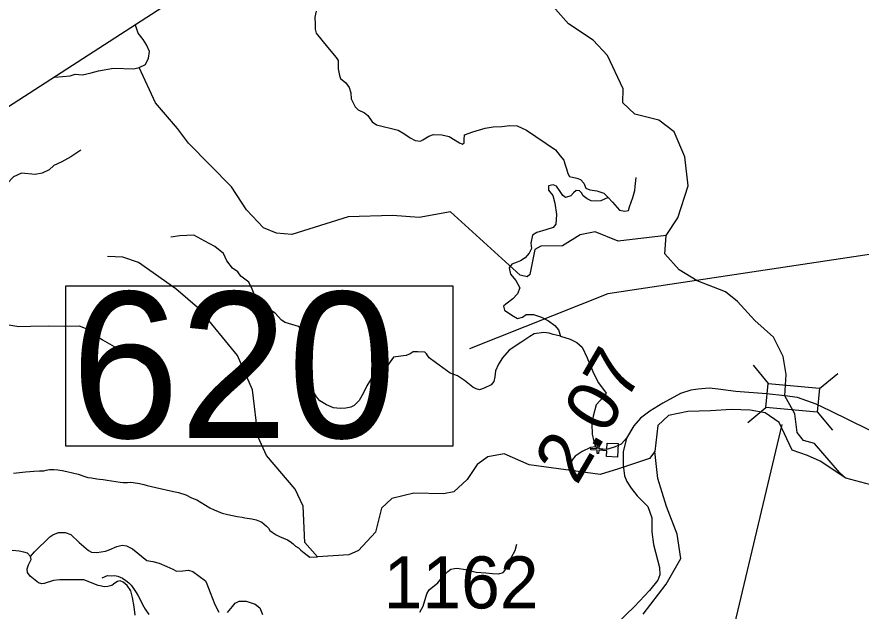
# Model space of a CAD drawing. Extents: x 1248089 to 1457196, y 820910 to 988753.
# Drawn here: x 1252912 to 1261020, y 869456 to 875158 of the extents above; entities that cross this region are included whole.
import ezdxf

# ---------------------------------------------------------------- set-up
doc = ezdxf.new("R2010")
doc.units = 0
for name, color, linetype in [('Exist Boundary Political CountyLine', 7, 'Continuous'), ('Exist Cultural Church CELL', 7, 'Continuous'), ('Exist Hydrographic Creek Single Shore', 7, 'Continuous'), ('Exist Hydrographic Misc Water Feature', 7, 'Continuous'), ('Exist Road Non-System Type 51', 7, 'Continuous'), ('Exist Road Secondary Structure Standard Bridge CELL', 7, 'Continuous'), ('Exist Road Secondary Structure Standard Bridge Number Label', 7, 'Continuous'), ('Exist Road Secondary Type 41 Attributed', 7, 'Continuous'), ('Exist Road Secondary Type 51 Attributed', 7, 'Continuous'), ('Prop GRAU CAT1 Cell', 7, 'Continuous'), ('Prop Lane Lines', 7, 'Continuous')]:
    doc.layers.add(name, color=color, linetype=linetype)

msp = doc.modelspace()

# ---------------------------------------------------------------- linework, layer by layer
at = {"layer": 'Exist Boundary Political CountyLine'}
msp.add_lwpolyline([(1272087, 895656.9), (1271079.1, 894111.7), (1270645.1, 893445.4), (1270071.1, 892564.9), (1269839.1, 892211.5), (1269310.1, 891393.6), (1268930.1, 890815.9), (1268447.1, 890082.3), (1267988.1, 889388.8), (1267175.1, 888170.6), (1266759.1, 887546.2), (1266505.1, 887165.9), (1265873.1, 886219.1), (1264802.2, 884614.3), (1263985.2, 883390.3), (1262147.2, 880635.4), (1261769.2, 880069.6), (1260071.2, 878960.9), (1254161.3, 875151.2), (1250985.3, 873104.2), (1248224.3, 871303)], dxfattribs=at)
at = {"layer": 'Exist Cultural Church CELL'}
msp.add_lwpolyline([(1258574.5, 870938.7), (1258576.9, 870995.6), (1258500.9, 870999), (1258499.4, 870967), (1258483.5, 870967.7), (1258484.9, 870999.7), (1258424.8, 871002.4), (1258425.5, 871018.4), (1258485.6, 871015.7), (1258487, 871047.7), (1258503, 871047), (1258501.6, 871015), (1258577.6, 871011.6), (1258580.3, 871069.2), (1258686.7, 871064.5), (1258680.9, 870934)], close=True, dxfattribs=at)
at = {"layer": 'Exist Hydrographic Creek Single Shore'}
for points in [[(1259326.3, 873814.3), (1259224.3, 874056), (1259077.3, 874167.3), (1258845.3, 874224.5), (1258731.3, 874335.1), (1258734.4, 874469.5), (1258584.4, 874787.8), (1258446.4, 874935), (1258208.3, 875090.7), (1258038.3, 875287.8), (1258016.3, 875386.7), (1257961.3, 875506.1), (1257896.3, 875572.9), (1257723.2, 875652), (1257687.3, 875895.6), (1257622.3, 875939.5), (1257281.3, 876005.5), (1257292.3, 876080.8), (1257395.3, 876219.8), (1257399.3, 876354.4), (1257352.3, 876496.5), (1257381.2, 876945.6), (1257399.3, 877004.4), (1257408.9, 877244.7)], [(1254086.2, 874671.1), (1254148.2, 874701.5), (1254177.9, 874760.8), (1254185.3, 874825.7), (1254155.7, 874888.7), (1254124.1, 874942.5), (1254077.8, 875001.8), (1254050.4, 875079.7)], [(1254559.3, 873945.9), (1254455.3, 874085.9), (1254244.3, 874333.1), (1254086.2, 874671.1)], [(1259148.4, 873059.6), (1258688.3, 873006.4), (1258465.3, 873096.2), (1258323.3, 873066.2), (1258153.3, 872961.3), (1257945.3, 872958.9), (1257885.3, 872927.3), (1257837.4, 872685.4), (1257812.3, 872662.8), (1257746.3, 872680.5), (1257077.3, 873288.1), (1256776.3, 873231.8), (1256518.4, 873253.5), (1256092.4, 873239), (1255554.3, 873069.2), (1255404.3, 873082), (1255280.4, 873133.8), (1255118.4, 873307.7), (1254974.3, 873527.3), (1254559.3, 873945.9)], [(1259148.4, 873059.6), (1259261.3, 873231.3), (1259360.4, 873537.9), (1259326.3, 873814.3)], [(1260287.6, 871522.6), (1260301, 871727.8), (1260271.2, 871899.7), (1260178.2, 872085.9), (1260000.7, 872246.1), (1259834.1, 872425.8), (1259718.4, 872519.6), (1259445.4, 872626.8), (1259273.3, 872732), (1259135.3, 872885.9), (1259148.4, 873059.6)], [(1260813.5, 870786.7), (1260573.6, 871063.1), (1260467.6, 871093.4), (1260404.8, 871171.3), (1260383.2, 871348.9), (1260287.6, 871522.6)], [(1260872.4, 870730.4), (1260626.5, 870896.2), (1260503.4, 870947.9), (1260357, 871001), (1260231.5, 871267.3), (1260099.6, 871358.3), (1259954.6, 871384.3), (1259775, 871390.8), (1259573.8, 871377.8), (1259356.5, 871370.3), (1259170.4, 871332.4), (1259067.4, 871236), (1259038.3, 870988.3)], [(1258926.5, 869427.1), (1259146.4, 869715.2), (1259287.1, 869960.8), (1259254.6, 870194.7), (1259150.8, 870460.3), (1259068.6, 870728.8), (1259038.3, 870988.3)], [(1261475.5, 870508.2), (1261162.5, 870655.7), (1260872.4, 870730.4), (1260813.5, 870786.7)]]:
    msp.add_lwpolyline(points, dxfattribs=at)
at = {"layer": 'Exist Hydrographic Misc Water Feature'}
for points in [[(1253276.3, 874580.8), (1253422.5, 874593.2), (1253471, 874607.8), (1253542.1, 874603.2), (1253625.5, 874621.8), (1253695.9, 874640.3), (1253840.7, 874666.9), (1254037, 874658.8), (1254086.2, 874671.1)], [(1259038.3, 870988.3), (1258988.6, 870921.2), (1258690.4, 870820.1), (1258513.4, 870767.8), (1257832.4, 870860.3), (1257593.4, 870966.8), (1257434.4, 870937.1), (1257332.4, 870863.7), (1257236.5, 870717.9), (1257108.4, 870602.2), (1257008.4, 870581.3), (1256724.4, 870587), (1256514.4, 870535.4), (1256412.5, 870445.5), (1256356.4, 870213.6), (1256193.5, 870036.3), (1256100.5, 869995.5), (1255800.4, 869978.5), (1255678.4, 870115.5), (1255662.4, 870463.8), (1255583.4, 870626.2), (1255308.3, 870950.2), (1255229.4, 871125.7), (1255174.3, 871579.8), (1255032.3, 871907.7), (1254668.4, 872351.5), (1254440.4, 872549.9), (1254079.4, 872800), (1253931.3, 872852.2), (1253781.3, 872858.5)], [(1252879.5, 870781), (1252937.6, 870787.5), (1252995.9, 870794.1), (1253038, 870796.9), (1253075.9, 870798), (1253130.3, 870802.6), (1253170.3, 870803.5), (1253194.4, 870808.9), (1253226.5, 870814.1), (1253246.7, 870815.5), (1253268.6, 870815), (1253304.6, 870812.1), (1253348.4, 870804.9), (1253392.2, 870795.8), (1253499.6, 870769.1), (1253565.1, 870749.3), (1253594.8, 870738.5), (1253628.8, 870733.7), (1253680.5, 870724.2), (1253704.5, 870723.6), (1253742.5, 870718.7), (1253780.3, 870711.7), (1253820.3, 870706.7), (1253862, 870699.6), (1253904, 870694.5)], [(1253904, 870694.5), (1253933.9, 870691.7), (1253973.9, 870690.7), (1254006, 870692), (1254028, 870691.3), (1254089.7, 870681.7), (1254131.6, 870670.6), (1254163.2, 870661.8), (1254205.2, 870652.7), (1254246.9, 870641.7), (1254416.1, 870605.3), (1254465.8, 870593.9), (1254535.3, 870572.2), (1254590.6, 870542.8), (1254640, 870523.4), (1254722.7, 870473.3), (1254766.2, 870448.1), (1254807.8, 870429.1), (1254885, 870397.1), (1254936.7, 870381.7), (1254982.5, 870374.4), (1255028.2, 870365.3), (1255076.1, 870358), (1255101.9, 870351.5), (1255169.7, 870341.6), (1255211.6, 870332.5), (1255241.3, 870319.8), (1255265, 870309.1), (1255288.6, 870290.6), (1255308, 870272), (1255327.5, 870251.5), (1255341.1, 870231.2), (1255364.5, 870212.5), (1255402.1, 870189.6), (1255433.5, 870172.8), (1255510.7, 870140.8), (1255538.4, 870124), (1255565.8, 870101.2), (1255589.3, 870080.7), (1255617, 870061.9), (1255640.3, 870041.3), (1255687.4, 870002.1), (1255726.7, 869975), (1255800.4, 869978.5)], [(1253732.1, 869776.3), (1253782.8, 869797), (1253818.7, 869796.1), (1253848.8, 869797.3), (1253880.7, 869790.5), (1253928.1, 869771.3), (1253959.6, 869750.4), (1253987.2, 869727.7), (1254008.5, 869705.1), (1254031.8, 869674.5), (1254056.8, 869635.8), (1254075.9, 869603.3), (1254100.9, 869560.7), (1254119.8, 869520.2), (1254144.7, 869475.5), (1254179.4, 869422.5)]]:
    msp.add_lwpolyline(points, dxfattribs=at)
at = {"layer": 'Exist Road Non-System Type 51'}
for points in [[(1255787.8, 875212.6), (1255773.7, 875156.1), (1255776, 875087.8), (1255778.4, 875040.7), (1255787.8, 875000.7), (1255896.1, 874866.5), (1255977.8, 874769.1), (1255996.6, 874740.9), (1255996.6, 874658.4), (1256010.8, 874597.2), (1256020.2, 874566.6), (1256071.9, 874524.2), (1256104.9, 874481.8), (1256119, 874430), (1256123.7, 874371.1), (1256161.4, 874295.8), (1256189.6, 874265.2), (1256250.8, 874236.9), (1256283.7, 874211), (1256323.7, 874149.8), (1256366.1, 874123.9), (1256573.2, 874072.1), (1256627.3, 874039.1), (1256690.8, 873996.7), (1256737.9, 873970.8), (1256787.3, 873966.1), (1256810.9, 873977.9), (1256867.3, 874013.2), (1256914.4, 874029.7), (1256992.1, 874027.3), (1257065, 874010.8), (1257163.8, 873949.6), (1257193.1, 873936), (1257207.2, 873950.1), (1257207.2, 873983.1), (1257211.9, 874025.4), (1257289.5, 874056.1), (1257409.6, 874089), (1257484.9, 874103.2), (1257569.6, 874107.9), (1257647.2, 874117.3), (1257715.5, 874112.6), (1257807.3, 874070.2), (1258084.9, 873884.1), (1258129, 873824.2), (1258164.3, 873784.1), (1258176, 873748.8), (1258190.1, 873699.4), (1258201.9, 873654.6), (1258218.4, 873626.4), (1258289, 873612.2), (1258326.6, 873598.1), (1258357.2, 873562.8), (1258376, 873513.3), (1258413.7, 873499.2), (1258481.9, 873489.8), (1258550.2, 873466.2), (1258590.2, 873423.8), (1258632.6, 873381.4), (1258698.4, 873303.7), (1258750.2, 873294.3), (1258785.5, 873301.4), (1258794.9, 873334.3), (1258827.9, 873423.8), (1258846.7, 873492.1), (1258849, 873529.8), (1258860.8, 873616.9)], [(1253527.3, 873880.3), (1253430.8, 873814.7), (1253344.6, 873766.4), (1253268.7, 873731.9), (1253223.8, 873690.5), (1253154.9, 873659.4), (1253089.3, 873645.6), (1252958.3, 873659.4), (1252879, 873624.9), (1252820.4, 873559.8), (1252786.1, 873519.4), (1252765.1, 873468.1), (1252765.1, 873409.8), (1252746.4, 873321.2)], [(1258590.2, 873423.8), (1258519.7, 873393.9), (1258477.8, 873389.3), (1258428.8, 873393.9), (1258389.2, 873412.6), (1258351.9, 873440.6), (1258333.3, 873470.9), (1258314.6, 873489.6), (1258282, 873491.9), (1258256.4, 873470.9), (1258230.7, 873440.6), (1258181.8, 873424.3), (1258153.8, 873442.9), (1258128.2, 873482.6), (1258095.6, 873533.9), (1258062.9, 873545.5), (1258016.3, 873538.5), (1258018.6, 873494.2), (1258060.6, 873445.2), (1258079.2, 873370.6), (1258095.6, 873263.3), (1258088.6, 873170), (1258062.9, 873137.4), (1257993, 873114.1), (1257906.8, 873090.7), (1257864.8, 873065.1), (1257848.5, 872988.1), (1257853.2, 872934.5), (1257832.2, 872890.2), (1257792.6, 872845.8), (1257748.6, 872816.5), (1257718.3, 872804.9), (1257664.7, 872786.2), (1257641.4, 872748.9), (1257653.1, 872688.3), (1257704.4, 872630), (1257741.7, 872557.7), (1257720.7, 872501.7), (1257674.1, 872452.7), (1257606.5, 872401.4), (1257585.5, 872382.7), (1257594.8, 872345.4), (1257664.7, 872296.4), (1257720.7, 872263.8), (1257769.6, 872275.4), (1257802.2, 872303.4), (1257874.5, 872303.4), (1257949.1, 872277.8), (1258019, 872240.5), (1258079.6, 872196.1), (1258112.2, 872156.5), (1258133.2, 872093.5)], [(1258133.2, 872093.5), (1258090.9, 872104.3), (1258062.9, 872109), (1258025.6, 872123), (1257974.4, 872130), (1257881.1, 872116), (1257836.9, 872090.3), (1257753, 872034.4), (1257638.8, 871959.7), (1257575.8, 871887.4), (1257536.2, 871824.4), (1257508.2, 871761.5), (1257501.2, 871705.5), (1257491.9, 871658.8), (1257466.3, 871628.5), (1257398.7, 871595.9), (1257354.4, 871579.5), (1257324.1, 871588.9), (1257291.5, 871605.2), (1257212.3, 871670.5), (1257144.7, 871712.5), (1257072.4, 871738.1), (1256932.6, 871840.8), (1256870.6, 871886.8), (1256845, 871926.4), (1256828.6, 871940.4), (1256763.4, 871945.1), (1256719.1, 871945.1), (1256688.8, 871926.4), (1256651.5, 871907.7), (1256600.2, 871903.1), (1256528, 871893.7), (1256497.7, 871849.4), (1256451.1, 871784.1), (1256411.5, 871767.8), (1256313.6, 871683.8), (1256274.6, 871617.1), (1256241.9, 871549.4), (1256200, 871477.1), (1256151, 871430.5), (1256118.4, 871414.2), (1256071.8, 871402.5), (1256015.9, 871400.2), (1255952.9, 871407.2), (1255885.4, 871435.2), (1255822.4, 871472.5), (1255789.8, 871512.1), (1255750.2, 871577.4), (1255738.5, 871642.7), (1255710.6, 871698.7), (1255680.3, 871768.7), (1255673.3, 871845.6), (1255680.3, 871948.3), (1255682.6, 872027.6), (1255668.6, 872076.5), (1255643, 872165.2), (1255615.8, 872187.2), (1255490, 872226.9), (1255452.7, 872247.9), (1255392.1, 872315.5), (1255357.1, 872338.8), (1255284.9, 872392.5), (1255205.6, 872460.1), (1255170.7, 872544.1), (1255140.4, 872611.7), (1255062, 872668.9), (1255033.1, 872712), (1254982.7, 872748.3), (1254927.5, 872817.3), (1254896.5, 872886.3), (1254813.7, 872955.3), (1254717.2, 873007.1), (1254610.2, 873062.3), (1254475.7, 873058.9), (1254390.9, 873044.7)], [(1252560.5, 872198.4), (1252653.9, 872205.6), (1252753.5, 872209.4), (1252854.9, 872199.8), (1252929.6, 872186.4), (1253044.5, 872190.2), (1253214.9, 872194.1), (1253366.1, 872190.2), (1253511.6, 872192.1), (1253584.4, 872163.4), (1253735.6, 872060), (1253823.7, 872008.2), (1253892.6, 871969.9), (1253997.9, 871925.8), (1254121.2, 871838.3), (1254171, 871809.6), (1254247.5, 871769.4), (1254293.5, 871708), (1254324.1, 871641)], [(1258133.2, 872093.5), (1258225.8, 872067), (1258291.1, 872034.4), (1258340, 871990.1), (1258389, 871887.5), (1258444.9, 871756.8), (1258496.2, 871649.6), (1258545.1, 871584.3), (1258573.1, 871546.9), (1258552.1, 871518.9), (1258475.2, 871435), (1258447.3, 871327.7), (1258433.3, 871250.7), (1258435.6, 871155.1), (1258454.2, 871082.8), (1258468.2, 871031.5)], [(1258468.2, 871031.5), (1258519.3, 871013.7), (1258542.6, 871009), (1258589.2, 871013.7), (1258661.5, 871037), (1258717.4, 871060.3), (1258766.4, 871114.7)], [(1258468.2, 871031.5), (1258421.4, 871027.7), (1258339.8, 870988), (1258274.6, 870941.4), (1258246.6, 870911.1), (1258232.6, 870873.8), (1258230.3, 870829.4)], [(1253041.7, 869980.4), (1253082.1, 870026), (1253227.9, 870170), (1253259, 870189.5), (1253313.5, 870210.9), (1253375.7, 870210.9), (1253430.2, 870191.5), (1253509.9, 870115.5), (1253601.3, 870037.7), (1253628.5, 870022.1), (1253681, 870018.2), (1253762.7, 870031.9), (1253797.7, 870043.5), (1253873.6, 870074.7), (1253924.1, 870088.3), (1253965, 870082.5), (1254021.4, 870053.3), (1254161.4, 869942.3), (1254218.8, 869931.1), (1254279.1, 869915.6), (1254351, 869884.4), (1254409.4, 869857.2), (1254446.3, 869839.7), (1254504.7, 869841.6), (1254561.1, 869849.4), (1254601.9, 869835.8), (1254724.4, 869746.3), (1254736.1, 869719), (1254767.2, 869635.3), (1254813.9, 869520.5), (1254852.8, 869444.6)], [(1256783.6, 869444.6), (1256813.6, 869504.7), (1256849.6, 869620.8), (1256871.6, 869658.8), (1256955.6, 869726.8), (1257007.6, 869792.9), (1257051.6, 869836.9), (1257079.6, 869858.9), (1257113.6, 869864.9), (1257141.6, 869866.9), (1257219.6, 869854.9), (1257321.6, 869830.9), (1257415.5, 869824.9), (1257479.5, 869816.9), (1257539.5, 869814.9), (1257583.5, 869826.9), (1257601.5, 869848.9), (1257625.5, 869902.9), (1257663.5, 869975), (1257697.5, 870039), (1257713.5, 870097.1)], [(1254935.8, 869443.4), (1254984.4, 869501.8), (1255007.7, 869533), (1255048.6, 869552.4), (1255114.7, 869550.5), (1255200.3, 869521.3), (1255247, 869486.2), (1255270.3, 869422)]]:
    msp.add_lwpolyline(points, dxfattribs=at)
at = {"layer": 'Exist Road Secondary Structure Standard Bridge CELL'}
for p, q in [((1259983, 871815.5), (1260127.2, 871641)), ((1260620.7, 871593.2), (1260795.1, 871737.5)), ((1259931, 871266.2), (1260105.4, 871410.5)), ((1260599.4, 871367.9), (1260743.6, 871193.5))]:
    msp.add_line(p, q, dxfattribs=at)
msp.add_lwpolyline([(1260127.2, 871641), (1260620.8, 871594.3), (1260599, 871363.8), (1260105.4, 871410.5)], close=True, dxfattribs=at)
at = {"layer": 'Exist Road Secondary Structure Standard Bridge Number Label'}
msp.add_line((1260257.9, 871245.8), (1258336.6, 863186.8), dxfattribs=at)
msp.add_lwpolyline([(1261972.1, 873008.7), (1258587.7, 872499.2), (1257259.5, 871971.5)], dxfattribs=at)
msp.add_lwpolyline([(1253381.8, 872576), (1257097.7, 872576), (1257097.7, 871039.6), (1253381.8, 871039.6)], close=True, dxfattribs=at)
at = {"layer": 'Exist Road Secondary Type 41 Attributed'}
msp.add_lwpolyline([(1254047.1, 869415.6), (1254039.6, 869497.5), (1254023.7, 869587.9), (1254007, 869651.4), (1253972.7, 869702.5), (1253933.4, 869734.2), (1253904.1, 869746.8), (1253878.2, 869739.3), (1253853.1, 869723.4), (1253823, 869703.3), (1253786.2, 869691.6), (1253751.9, 869689.1), (1253712.6, 869699.9), (1253694.2, 869702.5), (1253555, 869754.9), (1253448.9, 869757.2), (1253326.2, 869757.2), (1253264.8, 869750.1), (1253175.2, 869721.8), (1253151.6, 869719.4), (1253120.9, 869726.5), (1253040.7, 869792.7), (1253013.4, 869827), (1253011, 869862.4), (1253025.2, 869900.2), (1253051.1, 869952.1), (1253041.7, 869980.4), (1253013.4, 870011.1), (1252980.4, 870020.6), (1252933.2, 870032.4), (1252867.1, 870037.1)], dxfattribs=at)
at = {"layer": 'Exist Road Secondary Type 51 Attributed'}
for points in [[(1262915.3, 871836.6), (1262802.8, 871565.4), (1262718.3, 871373.8), (1262667.2, 871262), (1262595.2, 871125.5), (1262532.8, 871040.3), (1262489.2, 870998.6), (1262316.9, 870924.7), (1262129.4, 870862.1), (1261994.2, 870835.4), (1261882.5, 870825.9), (1261770.8, 870833.5), (1261651.5, 870858.2), (1261272.8, 871096.9), (1261093.5, 871196.7), (1260721.3, 871376.7), (1260588.7, 871441.1), (1260408.8, 871507.4), (1260287.6, 871522.6)], [(1260287.6, 871522.6), (1260111.5, 871539.7), (1259816.2, 871562.4), (1259645.7, 871585.1), (1259559.7, 871594.8), (1259455.6, 871587.2), (1259383.6, 871575.9), (1259285.2, 871545.5), (1259116.7, 871452.7), (1258991.7, 871375), (1258902.7, 871308.7), (1258836.4, 871234.8), (1258766.4, 871114.7), (1258736.1, 870984), (1258734.2, 870855.1), (1258747.4, 870754.7), (1258770.1, 870699.7), (1258811.8, 870637.2), (1258870.5, 870563.3), (1258923.5, 870508.3), (1258970.6, 870460.3), (1259008.5, 870350.4), (1259010.4, 870215.9), (1259027.4, 870096.5), (1259082.3, 869874.7), (1259088, 869804.6), (1259069.1, 869753.5), (1258988.2, 869652.7), (1258842.4, 869501), (1258673.9, 869336.2)]]:
    msp.add_lwpolyline(points, dxfattribs=at)

# ---------------------------------------------------------------- texts
at = {"layer": 'Exist Road Secondary Structure Standard Bridge Number Label'}
msp.add_text('620', height=1400, dxfattribs=at).set_placement((1253431.9, 871118.7))
at = {"layer": 'Prop GRAU CAT1 Cell'}
msp.add_text('2.07', height=500, rotation=59.73203, dxfattribs=at).set_placement((1258289.6, 870653.4))
at = {"layer": 'Prop Lane Lines'}
msp.add_text('1162', height=500, dxfattribs=at).set_placement((1256435.1, 869481.6))

doc.saveas('drawing.dxf')
